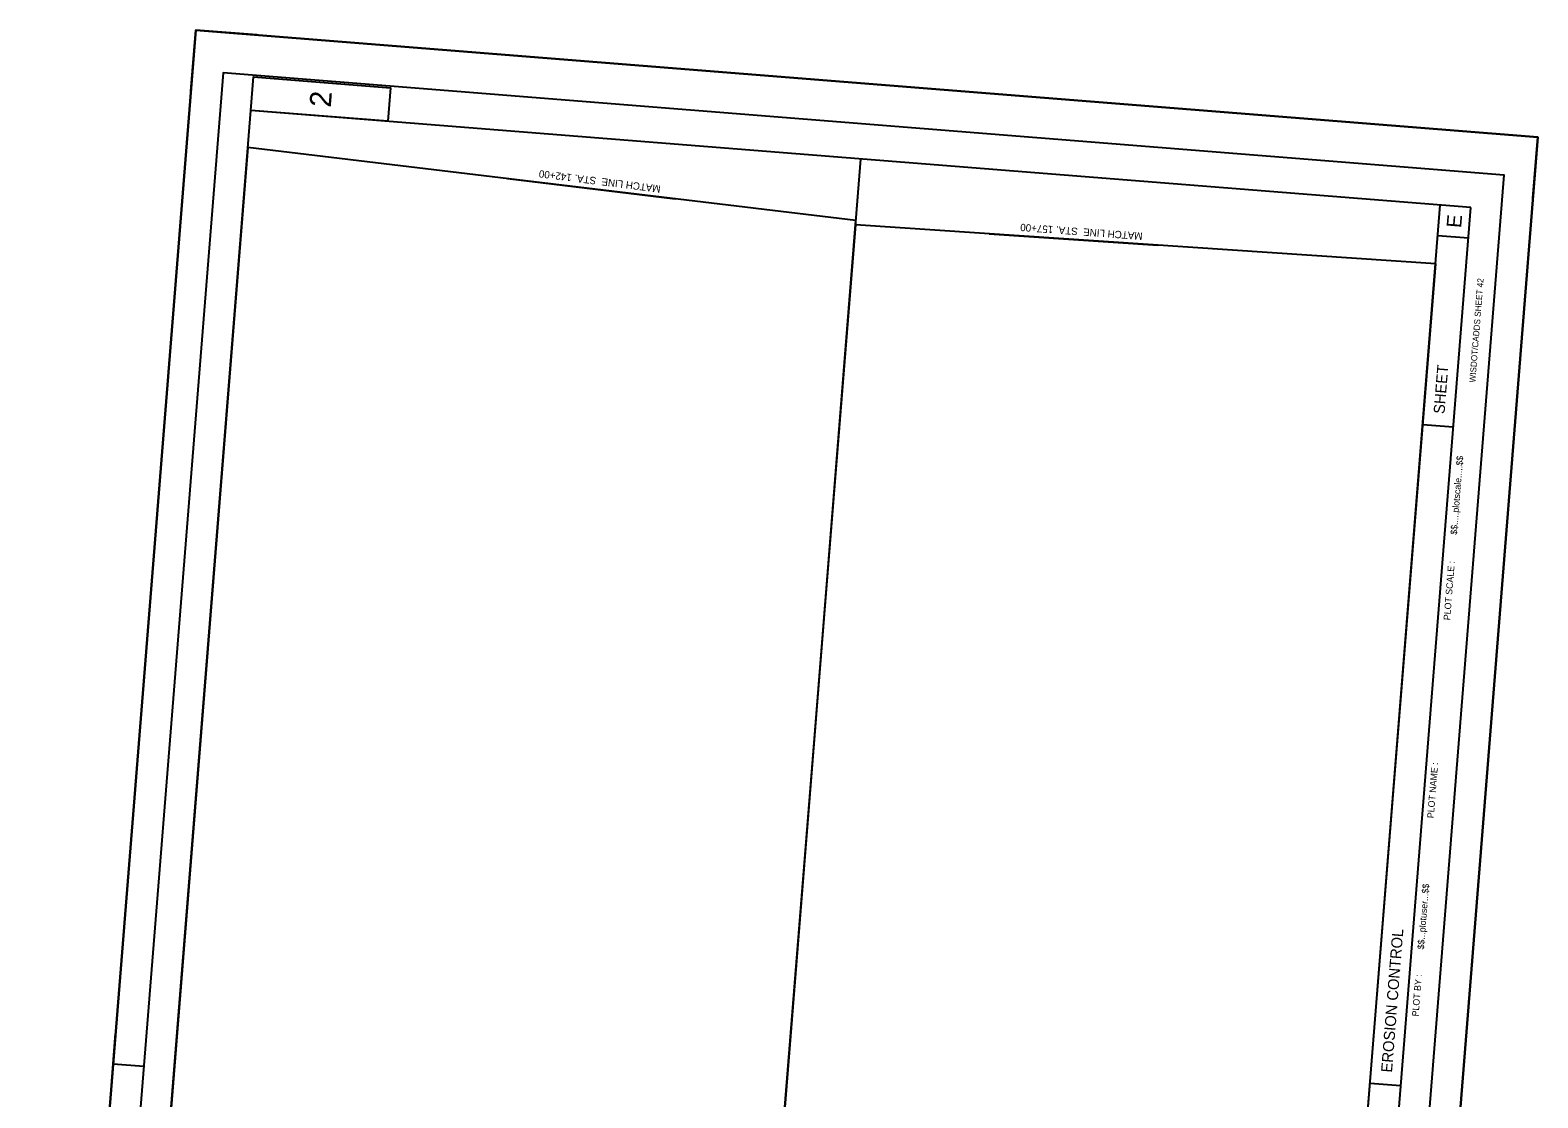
# Model space of a CAD drawing. Extents: x 360843 to 362075, y 137204 to 138986.
# Drawn here: x 360843 to 362075, y 138113 to 138986 of the extents above; entities that cross this region are included whole.
import ezdxf

# ---------------------------------------------------------------- set-up
doc = ezdxf.new("R2010")
doc.units = 0
for name, color, linetype in [('Default', 7, 'Continuous'), ('P_SHTIDX_3 [KAPUR_CADDS_LEVELS]', 7, 'Continuous'), ('P_SHTIDX_4 [KAPUR_CADDS_LEVELS]', 7, 'Continuous'), ('P_TXT_Plan 1 [KAPUR_CADDS_LEVELS]', 7, 'Continuous'), ('P_TXT_Plan 3 [KAPUR_CADDS_LEVELS]', 7, 'Continuous'), ('P_TXT_Plan 4 [KAPUR_CADDS_LEVELS]', 7, 'Continuous'), ('P_TXT_Plan 4_TEXT [KAPUR_CADDS_LEVELS]', 7, 'Continuous'), ('PLT_Sheet_Info', 7, 'Continuous')]:
    doc.layers.add(name, color=color, linetype=linetype)

msp = doc.modelspace()

# ---------------------------------------------------------------- linework, layer by layer
at = {"layer": 'Default'}
for points in [[(360898.9, 137361.2), (361400.8, 137365.7), (361517.7, 138830.6), (361020.9, 138890.2)], [(360898.9, 137361.2), (361400.8, 137365.7), (361517.7, 138830.6), (361020.9, 138890.2)], [(360898.9, 137361.2), (361400.8, 137365.7), (361517.7, 138830.6), (361020.9, 138890.2)], [(360898.9, 137361.2), (361400.8, 137365.7), (361517.7, 138830.6), (361020.9, 138890.2)], [(360898.9, 137361.2), (361400.8, 137365.7), (361517.7, 138830.6), (361020.9, 138890.2)], [(360898.9, 137361.2), (361400.8, 137365.7), (361517.7, 138830.6), (361020.9, 138890.2)], [(360898.9, 137361.2), (361400.8, 137365.7), (361517.7, 138830.6), (361020.9, 138890.2)], [(360898.9, 137361.2), (361400.8, 137365.7), (361517.7, 138830.6), (361020.9, 138890.2)], [(360898.9, 137361.2), (361400.8, 137365.7), (361517.7, 138830.6), (361020.9, 138890.2)], [(361397.4, 137334.1), (361871.2, 137295.9), (361991.4, 138795.1), (361517.4, 138826.9)], [(361397.4, 137334.1), (361871.2, 137295.9), (361991.4, 138795.1), (361517.4, 138826.9)], [(361397.4, 137334.1), (361871.2, 137295.9), (361991.4, 138795.1), (361517.4, 138826.9)], [(361397.4, 137334.1), (361871.2, 137295.9), (361991.4, 138795.1), (361517.4, 138826.9)], [(361397.4, 137334.1), (361871.2, 137295.9), (361991.4, 138795.1), (361517.4, 138826.9)], [(361397.4, 137334.1), (361871.2, 137295.9), (361991.4, 138795.1), (361517.4, 138826.9)], [(361397.4, 137334.1), (361871.2, 137295.9), (361991.4, 138795.1), (361517.4, 138826.9)], [(361397.4, 137334.1), (361871.2, 137295.9), (361991.4, 138795.1), (361517.4, 138826.9)], [(361397.4, 137334.1), (361871.2, 137295.9), (361991.4, 138795.1), (361517.4, 138826.9)]]:
    msp.add_lwpolyline(points, close=True, dxfattribs=at)
at = {"layer": 'P_SHTIDX_3 [KAPUR_CADDS_LEVELS]'}
msp.add_lwpolyline([(360843.1, 137291.4), (360978.4, 138986), (362074.9, 138898.5), (361939.7, 137203.9), (360843.1, 137291.4)], dxfattribs=at)
at = {"layer": 'P_SHTIDX_4 [KAPUR_CADDS_LEVELS]'}
for p, q in [((360974.4, 138936.2), (360978.4, 138986)), ((361028.2, 138982.1), (360978.4, 138986)), ((360898, 137350.5), (361023.3, 138920.5)), ((362020.1, 138841), (361023.3, 138920.5)), ((362074.9, 138898.5), (362025, 138902.5)), ((362070.9, 138848.7), (362074.9, 138898.5)), ((361470, 138232.4), (361521.7, 138880.7)), ((361869.9, 137272.9), (361995.2, 138843)), ((361894.8, 137271), (362020.1, 138841)), ((362018.1, 138816), (361993.2, 138818)), ((362005.8, 138661.5), (361980.9, 138663.5)), ((360909, 138116.3), (360912.9, 138166.1)), ((360910.9, 138141.2), (360935.9, 138139.2)), ((361962.8, 138123.3), (361937.9, 138125.2))]:
    msp.add_line(p, q, dxfattribs=at)
msp.add_lwpolyline([(361023.3, 138920.5), (361025.5, 138947.9), (361137.6, 138939), (361135.4, 138911.6)], close=True, dxfattribs=at)
at = {"layer": 'P_TXT_Plan 1 [KAPUR_CADDS_LEVELS]'}
msp.add_line((361396.4, 137310.7), (361521.7, 138880.7), dxfattribs=at)
at = {"layer": 'P_TXT_Plan 4 [KAPUR_CADDS_LEVELS]'}
for p, q in [((361233, 138864.8), (361370.2, 138848.3)), ((361626.5, 138819.6), (361764.3, 138810.3))]:
    msp.add_line(p, q, dxfattribs=at)
at = {"layer": 'P_TXT_Plan 4_TEXT [KAPUR_CADDS_LEVELS]'}
msp.add_lwpolyline([(360843.1, 137291.4), (360978.4, 138986), (362074.9, 138898.5), (361939.7, 137203.9)], close=True, dxfattribs=at)
at = {"layer": 'PLT_Sheet_Info'}
for points in [[(361939.7, 137203.9), (362074.9, 138898.5), (360978.4, 138986), (360843.1, 137291.4)], [(361915.7, 137217.9), (362047.3, 138867.6), (361000.7, 138951.2), (360869, 137301.4)]]:
    msp.add_lwpolyline(points, close=True, dxfattribs=at)

# ---------------------------------------------------------------- texts
at = {"layer": 'P_SHTIDX_4 [KAPUR_CADDS_LEVELS]'}
for s, height, p in [('2', 17.5, (361088.7, 138922.5)), ('E', 12, (362012.2, 138824.1)), ('WISDOT/CADDS SHEET 42', 5, (362023.8, 138697.9)), ('SHEET ', 9, (361998.6, 138672.1)), ('$$.....plotscale.....$$', 5.4, (362008.8, 138573.5)), ('PLOT SCALE : ', 5.4, (362003.2, 138503.6)), ('PLOT NAME :                      ', 5.4, (361989.8, 138341.8)), ('$$...plotuser...$$', 5.4, (361981.8, 138234.6)), ('EROSION CONTROL', 9, (361955.7, 138133.9)), ('PLOT BY :', 5.4, (361977.4, 138179.8))]:
    msp.add_text(s, height=height, rotation=85.4379, dxfattribs=at).set_placement(p)
at = {"layer": 'P_TXT_Plan 3 [KAPUR_CADDS_LEVELS]'}
for s, rotation, p in [('MATCH LINE  STA. 142+00', 172.7522, (361358.5, 138859.1)), ('MATCH LINE  STA. 157+00', 175.7547, (361752.1, 138820.5))]:
    msp.add_text(s, height=6, rotation=rotation, dxfattribs=at).set_placement(p)

doc.saveas('drawing.dxf')
